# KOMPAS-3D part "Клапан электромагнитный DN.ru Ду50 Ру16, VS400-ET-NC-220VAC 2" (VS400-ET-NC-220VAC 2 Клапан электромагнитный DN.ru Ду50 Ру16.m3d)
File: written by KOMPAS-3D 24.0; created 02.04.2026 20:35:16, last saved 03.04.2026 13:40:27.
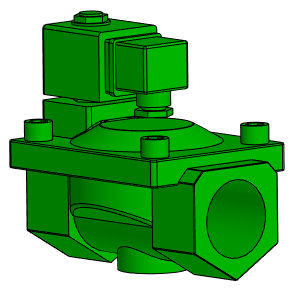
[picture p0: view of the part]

Document properties: Автор: artio; Полное имя файла: C:\Users\artio\OneDrive\Рабочий стол\Клапан электромагнитный DN.ru\VS400-ET-NC-220VAC 2 Клапан электромагнитный DN.ru Ду50 Ру16.m3d

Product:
- Body: Тело 1  | qty 1
    Масса: 7.119215
- Part/product: Клапан электромагнитный DN.ru Ду50 Ру16  | designation VS400-ET-NC-220VAC 2
    Масса: 3.509
    Раздел спецификации: Прочие изделия
    Примечание: D130-04696
    additional columns: ef56311e-7521-43dc-8291-0e6108b3d81d; VS400-ET-NC-220VAC 2; artio; c; Шероховатость не задана; Да

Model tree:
1. Операция без истории:1

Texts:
  VS400-ET-NC-220VAC 2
